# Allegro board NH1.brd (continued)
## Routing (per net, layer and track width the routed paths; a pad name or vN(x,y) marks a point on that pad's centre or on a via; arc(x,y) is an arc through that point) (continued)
M0_DATA45: length 17.9
  TOP w0.102: U1.R22 v1(15.4,58.77)
  BOTTOM w0.102: 15.71,60.05 15.71,59.76 15.73,59.74 15.73,59.1 v1(15.4,58.77)
  BOTTOM w0.14: 15.71,60.05 15.71,62.79 14.51,63.99 14.51,64.19 15,64.67 15,64.81 14.74,65.07 14.74,65.21 14.84,65.31 14.99,65.31 15.24,65.06 15.38,65.06 15.48,65.16 15.48,65.3 15.23,65.55 15.23,65.69 15.33,65.79 15.47,65.79 15.72,65.54 15.87,65.54 16.01,65.69 17.38,65.69 18.53,66.83 19.49,66.83 20.15,67.49 20.15,69.55 19.75,69.96 U1AM4.C2
M0_DATA46: length 17.6
  TOP w0.102: U1.V22 v1(17.4,58.77)
  BOTTOM w0.14: U1AM4.A7 23.75,68.05 23.75,66.27 23.62,66.15 23.48,66.15 23.22,66.41 23.08,66.41 22.98,66.31 22.98,66.17 23.24,65.91 23.24,65.77 22.55,65.08 20.99,65.08 20.19,64.28 20.19,64.14 20.6,63.74 20.6,63.59 20.5,63.49 20.35,63.49 19.95,63.9 19.81,63.9 19.71,63.8 19.71,63.66 20.11,63.25 20.11,63.11 20.01,63.01 19.87,63.01 19.47,63.41 19.32,63.41 19.06,63.15 19.06,61.59 18.34,60.87 17.54,60.87 17.4,60.73 v1(17.4,58.77)
M0_DATA47: length 18
  TOP w0.102: v1(16.08,61.55) 15.73,61.21 U1.T25
  BOTTOM w0.14: v1(16.08,61.55) 16.08,62.96 16.17,63.05 16.17,63.19 15.19,64.17 15.19,64.31 15.29,64.41 15.44,64.41 16.41,63.44 16.55,63.44 16.65,63.54 16.65,63.68 15.68,64.66 15.68,64.8 15.78,64.9 15.92,64.9 16.9,63.92 17.04,63.92 17.15,64.03 17.15,64.23 16.32,65.05 16.32,65.19 16.46,65.33 16.7,65.33 17.08,64.95 17.26,64.95 18.78,66.48 19.59,66.48 20.55,67.43 U1AM4.A3
M0_DATA48: length 22.8
  TOP w0.102: U1.AB22 v1(20.04,58.77)
  IN1 w0.102: v1(20.04,58.77) 21.34,60.07 21.35,60.2 21.16,60.38 21.16,60.5 21.25,60.59 21.38,60.59 21.56,60.41 21.69,60.41 21.8,60.53 21.8,60.91 21.41,61.31 21.41,61.43 21.5,61.52 21.62,61.52 21.94,61.21 22.06,61.21 22.15,61.3 22.15,61.43 21.84,61.74 21.84,61.86 21.93,61.95 22.06,61.95 22.37,61.64 22.49,61.64 22.58,61.73 22.58,61.86 22.27,62.17 22.27,62.3 22.36,62.39 22.49,62.39 22.8,62.07 22.92,62.07 23.01,62.16 23.01,62.29 22.7,62.6 22.7,62.73 22.79,62.82 22.92,62.82 23.23,62.5 23.36,62.5 23.48,62.63 23.48,63.1 24.24,63.86 24.24,70.44 23.76,70.92 23.76,73.17 v1(24.15,73.56)
  BOTTOM w0.14: U1AM4.H7 23.75,73.96 v1(24.15,73.56)
M0_DATA49: length 21.9
  TOP w0.102: U1.AC22 v1(20.7,58.77)
  IN1 w0.102: v1(20.7,58.77) 22.11,60.18 22.11,60.79 22.47,61.15 22.6,61.15 22.87,60.89 22.99,60.89 23.08,60.97 23.08,61.1 22.82,61.37 22.82,61.49 22.9,61.58 23.03,61.58 23.3,61.32 23.42,61.32 23.51,61.41 23.51,61.53 23.25,61.8 23.25,61.93 23.83,62.5 23.83,63.01 24.56,63.74 24.56,66.15 24.65,66.23 24.91,66.23 25,66.32 25,66.45 24.91,66.54 24.65,66.54 24.56,66.63 24.56,66.78 24.65,66.86 24.91,66.86 25,66.95 25,67.08 24.91,67.17 24.65,67.17 24.56,67.26 24.56,68.46 24.65,68.55 24.91,68.55 25,68.64 25,68.76 24.91,68.85 24.65,68.85 24.56,68.94 24.56,69.07 24.65,69.16 24.91,69.16 25,69.25 25,69.37 24.91,69.46 24.65,69.46 24.56,69.55 24.56,69.68 24.65,69.77 24.91,69.77 25,69.85 25,69.98 24.91,70.07 24.65,70.07 24.56,70.16 24.56,70.29 24.65,70.38 24.91,70.38 25,70.46 25,70.59 24.91,70.68 24.65,70.68 24.56,70.77 24.56,71.55 v1(24.15,71.96)
  BOTTOM w0.14: U1AM4.F8 v1(24.15,71.96)
M0_DATA50: length 22.6
  TOP w0.102: U1.Y19 v1(18.75,56.78)
  IN1 w0.102: v1(17.96,72.05) 18.6,72.05 18.93,71.71 18.93,62.46 17.06,60.59 17.06,56.58 17.31,56.33 18.3,56.33 v1(18.75,56.78)
  BOTTOM w0.14: U1AM4.G2 19.34,73.56 18.65,73.56 18.12,73.03 18.12,72.72 17.91,72.51 17.91,72.1 v1(17.96,72.05)
M0_DATA51: length 21.5
  TOP w0.102: v1(21.32,58.76) 21.02,58.46 U1.AD22
  IN1 w0.102: v1(24.15,72.76) 24.56,72.34 25.13,72.34 25.32,72.15 25.32,69.86 25.41,69.77 25.68,69.77 25.77,69.68 25.77,69.56 25.68,69.47 25.41,69.47 25.32,69.38 25.32,68.45 25.41,68.36 25.7,68.36 25.79,68.27 25.79,68.15 25.7,68.06 25.41,68.06 25.32,67.97 25.32,67.84 25.41,67.75 25.7,67.75 25.79,67.66 25.79,67.54 25.7,67.45 25.41,67.45 25.32,67.36 25.32,66.13 24.93,65.74 24.93,62.35 24.79,62.21 24.66,62.21 24.37,62.49 24.25,62.49 24.16,62.41 24.16,62.28 24.44,61.99 24.44,61.87 24.36,61.78 24.23,61.78 23.94,62.06 23.82,62.06 23.73,61.97 23.73,61.85 24.01,61.56 24.01,61.44 21.33,58.76 v1(21.32,58.76)
  BOTTOM w0.14: U1AM4.F7 v1(24.15,72.76)
M0_DATA52: length 22.2
  TOP w0.102: U1.AA22 v1(19.38,58.77)
  IN1 w0.102: v1(25.85,74.17) 25.55,73.87 25.55,72.75 26.1,72.19 26.1,66.49 25.23,65.61 25.23,62.19 21.45,58.4 19.75,58.4 v1(19.38,58.77)
  BOTTOM w0.14: U1AM4.H8 24.9,74.31 25.58,74.31 v1(25.85,74.17)
M0_DATA53: length 22.9
  TOP w0.102: U1.Y23 18.7,58.78 v1(18.72,58.78)
  IN1 w0.102: v1(21.32,71.56) 20.83,71.56 20.57,71.31 20.57,70.3 20.69,70.19 21.32,70.19 21.42,70.08 21.42,69.96 21.33,69.87 20.7,69.87 20.61,69.78 20.61,69.66 20.7,69.57 21.33,69.57 21.42,69.48 21.42,68.45 21.33,68.36 20.6,68.36 20.51,68.27 20.51,68.15 20.6,68.06 21.33,68.06 21.42,67.97 21.42,67.39 21.88,66.93 21.88,65.26 21.97,65.17 22.65,65.17 22.74,65.08 22.74,64.95 22.65,64.86 21.97,64.86 21.88,64.78 21.88,64.65 21.97,64.56 22.65,64.56 22.74,64.47 22.74,64.34 22.65,64.25 21.97,64.25 18.72,61 v1(18.72,58.78)
  BOTTOM w0.14: U1AM4.E3 20.86,71.56 v1(21.32,71.56)
M0_DATA54: length 23.1
  TOP w0.102: U1.Y20 v1(18.06,57.47)
  IN1 w0.102: v1(18.06,57.47) 17.73,57.8 17.73,59.75 17.56,59.91 17.56,60.66 19.31,62.42 19.31,62.54 21.14,64.37 21.14,65.21 21.05,65.3 20.83,65.3 20.74,65.39 20.74,65.51 20.83,65.6 21.05,65.6 21.14,65.69 21.14,65.83 21.05,65.92 19.84,65.92 19.75,66.01 19.75,66.18 19.84,66.26 20.29,66.26 20.38,66.35 20.38,66.48 20.29,66.57 19.84,66.57 19.75,66.66 19.75,71.42 20.88,72.55 v1(21.52,72.55)
  BOTTOM w0.14: U1AM4.H3 21.52,72.98 v1(21.52,72.55)
M0_DATA55: length 22.3
  TOP w0.102: U1.Y21 v1(18.7,57.46)
  IN1 w0.102: v1(20.15,71.2) 20.15,69.35 20.24,69.26 20.57,69.26 20.66,69.17 20.66,69.05 20.57,68.96 20.24,68.96 20.15,68.87 20.15,67.73 20.24,67.64 21.03,67.64 21.12,67.55 21.12,67.42 21.03,67.34 20.24,67.34 20.15,67.25 20.15,67.04 20.25,66.93 21.45,66.93 21.55,66.83 21.55,66.65 21.46,66.57 20.77,66.57 20.69,66.48 20.69,66.35 20.77,66.26 21.46,66.26 21.55,66.17 21.55,64.29 18.39,61.13 18.39,57.79 v1(18.7,57.46)
  BOTTOM w0.14: U1AM4.F2 20.15,71.95 v1(20.15,71.2)
M0_DATA56: length 24.5
  TOP w0.102: U1.T22 v1(16.06,58.77)
  TOP w0.14: U1AM3.F7 20.97,71.94 21.47,71.94 21.72,71.69 21.72,71.07 v1(21.33,70.68)
  IN2 w0.102: v1(21.33,70.68) 16.42,65.77 16.42,65.54 16.51,65.45 17.14,65.45 17.23,65.36 17.23,65.24 17.14,65.15 16.51,65.15 16.42,65.06 16.42,64.93 16.51,64.84 17.14,64.84 17.23,64.75 17.23,64.63 17.14,64.54 16.51,64.54 16.42,64.45 16.42,64.32 16.51,64.23 17.14,64.23 17.23,64.14 17.23,64.02 17.14,63.93 16.51,63.93 16.42,63.84 16.42,63.71 16.51,63.62 17.14,63.62 17.23,63.53 17.23,63.41 17.14,63.32 16.51,63.32 16.42,63.23 16.42,63.1 16.51,63.01 17.14,63.01 17.23,62.92 17.23,62.8 17.14,62.71 16.51,62.71 16.42,62.62 16.42,60.74 15.73,60.05 15.73,59.1 v1(16.06,58.77)
M0_DATA57: length 25.1
  TOP w0.102: U1.T20 v1(16.06,57.47)
  TOP w0.14: v1(17.97,71.18) 18.76,71.96 19.14,71.96 19.54,72.36 U1AM3.F8
  IN2 w0.102: v1(16.06,57.47) 15.2,57.47 14.88,57.16 14.61,57.16 14.41,57.35 14.41,59.19 14.51,59.29 14.51,60.43 14.31,60.63 14.31,62.72 14.74,63.16 14.98,63.16 15.07,63.25 15.07,63.37 14.98,63.46 14.53,63.46 14.44,63.55 14.44,63.68 14.53,63.77 14.98,63.77 15.07,63.85 15.07,63.98 14.98,64.07 14.53,64.07 14.44,64.16 14.44,64.29 14.53,64.38 14.98,64.38 15.07,64.46 15.07,64.59 14.98,64.68 14.53,64.68 14.44,64.77 14.44,64.9 14.53,64.98 14.98,64.98 15.07,65.07 15.07,65.2 14.98,65.29 14.53,65.29 14.44,65.38 14.44,65.51 14.53,65.59 14.98,65.59 15.07,65.68 15.07,65.81 14.98,65.9 14.6,65.9 14.51,65.99 14.51,66.45 16.85,68.79 16.85,70.06 v1(17.97,71.18)
M0_DATA58: length 23
  TOP w0.102: U1.W20 v1(18.04,56.79)
  TOP w0.14: U1AM3.F2 24.55,72.36 v1(24.95,71.96)
  IN2 w0.102: v1(18.04,56.79) 18.37,57.12 19.56,57.12 19.71,57.27 19.71,59.73 19.92,59.95 19.92,60.61 21.28,61.97 21.28,63.72 21.73,64.17 21.73,64.3 21.21,64.82 21.21,64.94 21.3,65.03 21.42,65.03 21.95,64.51 22.07,64.51 22.16,64.6 22.16,64.73 21.64,65.25 21.64,65.37 21.73,65.46 21.86,65.46 22.38,64.94 22.5,64.94 24.57,67.01 24.57,71.59 v1(24.95,71.96)
M0_DATA59: length 24
  TOP w0.102: U1.V20 v1(16.72,56.79)
  TOP w0.14: U1AM3.H8 19.75,73.96 19.39,74.31 18.62,74.31 17.74,73.44 v1(17.74,72.88)
  IN2 w0.102: v1(16.72,56.79) 16.38,57.13 15.28,57.13 15,56.85 14.54,56.85 13.75,57.64 13.75,68.89 v1(17.74,72.88)
M0_DATA60: length 24.1
  TOP w0.102: U1.U21 v1(16.73,58.12)
  TOP w0.14: U1AM3.H3 24.05,74.26 v1(24.15,74.36)
  IN2 w0.102: v1(16.73,58.12) 17.39,58.12 17.73,58.46 17.73,59.67 17.93,59.87 18.15,59.87 19.64,61.37 19.64,61.93 19.73,62.02 20.06,62.02 20.15,62.11 20.15,62.24 20.06,62.33 19.73,62.33 19.64,62.42 19.64,62.54 19.73,62.63 20.06,62.63 20.15,62.72 20.15,62.85 20.06,62.94 19.73,62.94 19.64,63.03 19.64,63.15 19.73,63.24 20.06,63.24 20.15,63.33 20.15,63.46 20.06,63.55 19.73,63.55 19.64,63.64 19.64,63.76 19.73,63.85 20.06,63.85 20.15,63.94 20.15,64.07 20.06,64.16 19.73,64.16 19.64,64.24 19.64,64.44 23.75,68.55 23.75,73.97 v1(24.15,74.36)
M0_DATA61: length 24.1
  TOP w0.102: U1.W21 v1(18.06,58.12)
  TOP w0.14: v1(24.15,71.16) 23.75,71.56 U1AM3.E3
  IN2 w0.102: v1(24.15,71.16) 24.15,68.46 23.37,67.68 23.37,67.56 23.84,67.09 23.84,66.96 23.75,66.87 23.62,66.87 23.15,67.34 23.02,67.34 22.93,67.25 22.93,67.13 23.4,66.66 23.4,66.53 23.32,66.44 23.19,66.44 22.72,66.91 22.59,66.91 22.5,66.82 22.5,66.69 22.97,66.22 22.97,66.1 22.88,66.01 22.76,66.01 22.29,66.48 22.16,66.48 20.48,64.8 20.48,64.51 20.57,64.42 20.88,64.42 20.97,64.33 20.97,64.21 20.88,64.12 20.57,64.12 20.48,64.03 20.48,63.9 20.57,63.81 20.88,63.81 20.97,63.72 20.97,63.6 20.88,63.51 20.57,63.51 20.48,63.42 20.48,63.29 20.57,63.2 20.88,63.2 20.97,63.11 20.97,62.99 20.88,62.9 20.57,62.9 20.48,62.81 20.48,62.68 20.57,62.59 20.88,62.59 20.97,62.5 20.97,62.38 20.88,62.29 20.57,62.29 20.48,62.2 20.48,61.73 18.39,59.63 18.39,58.45 v1(18.06,58.12)
M0_DATA62: length 24.5
  TOP w0.102: U1.U20 v1(16.73,57.47)
  TOP w0.14: U1AM3.G2 v1(24.95,73.56)
  IN2 w0.102: v1(16.73,57.47) 17.07,57.14 17.07,56.53 17.17,56.43 18.97,56.43 19.29,56.75 19.72,56.75 20.15,57.18 20.15,57.46 20.76,58.07 21.24,58.07 21.68,58.5 21.68,63.17 25.35,66.85 25.35,73.16 v1(24.95,73.56)
M0_DATA63: length 24.9
  TOP w0.102: U1.T21 v1(16.06,58.12)
  TOP w0.14: U1AM3.H7 20.15,73.56 18.74,73.56 18.38,73.2 v1(18.38,72.41)
  IN2 w0.102: v1(16.06,58.12) 15.59,58.12 15.07,58.64 15.07,59.1 15,59.17 15,60.97 15.4,61.37 15.4,61.95 15.49,62.04 15.97,62.04 16.06,62.13 16.06,62.26 15.97,62.35 15.49,62.35 15.4,62.43 15.4,62.56 15.49,62.65 15.97,62.65 16.06,62.74 16.06,62.87 15.97,62.96 15.49,62.96 15.4,63.04 15.4,63.17 15.49,63.26 15.97,63.26 16.06,63.35 16.06,63.48 15.97,63.56 15.49,63.56 15.4,63.65 15.4,63.78 15.49,63.87 15.97,63.87 16.06,63.96 16.06,64.09 15.97,64.17 15.49,64.17 15.4,64.26 15.4,66.88 18.78,70.26 18.78,71.05 18.38,71.46 v1(18.38,72.41)
M0_DM0: length 18.2
  TOP w0.102: U1.A20 5.33,57.61 4.49,57.61 4.48,57.6
  TOP w0.14: v1(4.24,57.15) 4.24,57.49 4.36,57.6 4.48,57.6
  BOTTOM w0.14: v1(4.24,57.15) 4.43,57.33 4.43,61.52 6.94,64.04 6.94,70.21 6.39,70.76 5.75,70.76 5.75,70.76 U1AM2.D3
M0_DM1: length 19.6
  TOP w0.102: U1.D21 v1(7.47,58.1)
  IN1 w0.102: v1(7.47,58.1) 7.14,58.43 7.14,59.12 7,59.26 7,61.86 6.91,61.95 6.42,61.95 6.33,62.04 6.33,62.17 6.42,62.26 6.91,62.26 7,62.35 7,62.47 6.91,62.56 6.42,62.56 6.33,62.65 6.33,62.78 6.42,62.87 6.91,62.87 7,62.96 7,63.08 6.91,63.17 6.42,63.17 6.33,63.26 6.33,63.39 6.42,63.48 6.91,63.48 7,63.56 7,63.69 6.91,63.78 6.42,63.78 6.33,63.87 6.33,64 6.42,64.09 6.91,64.09 7,64.17 7,70.75 7.77,71.53 v1(7.78,71.53)
  BOTTOM w0.14: v1(7.78,71.53) 8.51,71.56 U1AM2.E7
M0_DM2: length 13.6
  TOP w0.14: U1.D25 7.81,60.43 7.81,61.24 5.7,63.35 5.7,65.16 6.46,65.92 7.55,65.92 7.78,66.15 7.78,67.85 7.17,68.46 7.17,69.43 U1AM1.D3
M0_DM3: length 21.3
  TOP w0.102: U1.F19 9.12,56.45 v1(9.43,56.76)
  TOP w0.14: U1AM1.E7 v1(5.71,71.16)
  IN2 w0.102: v1(5.71,71.16) 5.71,70.79 5.39,70.47 5.39,69.73 6.38,68.74 6.38,68.61 6.1,68.33 6.1,68.21 6.19,68.12 6.32,68.12 6.6,68.4 6.73,68.4 6.82,68.31 6.82,68.18 6.54,67.9 6.54,67.78 6.62,67.69 6.75,67.69 7.03,67.97 7.16,67.97 7.25,67.88 7.25,67.75 6.97,67.47 6.97,67.34 7.06,67.25 7.18,67.25 7.46,67.53 7.59,67.53 7.68,67.44 7.68,67.32 7.4,67.04 7.4,66.91 7.49,66.82 7.61,66.82 7.89,67.1 8.02,67.1 9.38,65.74 9.38,65.24 9.62,65 9.62,61.32 9.83,61.12 9.83,57.16 v1(9.43,56.76)
M0_DM4: length 13.6
  TOP w0.102: 20.7,60.81 20.7,60.23 20.37,59.9 U1.AC24
  TOP w0.14: 20.7,60.81 20.7,61.17 21.22,61.69 21.22,62.82 22.08,63.68 22.95,63.68 23.43,64.17 23.43,66.35 22.92,66.86 22.92,67.9 22.57,68.25 22.57,69.58 U1AM3.D3
M0_DM5: length 15.1
  TOP w0.102: v1(17.84,62.36) 17.84,61.35 17.46,60.97 17.46,60.14 U1.V24
  BOTTOM w0.14: v1(17.84,62.36) 17.49,62.72 17.49,63.4 21.37,67.29 22.36,67.29 22.62,67.54 22.62,67.92 22.16,68.38 22.16,69.32 20.89,70.59 20.72,70.59 20.55,70.76 U1AM4.D3
M0_DM6: length 23
  TOP w0.102: U1.Y22 v1(18.72,58.13)
  IN1 w0.102: v1(23.35,71.16) 22.95,71.56 21.88,71.56 21.73,71.4 21.73,67.62 21.98,67.37 23.05,67.37 23.15,67.26 23.15,67.11 23.06,67.02 22.27,67.02 22.18,66.93 22.18,66.8 22.27,66.71 23.06,66.71 23.15,66.62 23.15,66.5 23.06,66.41 22.27,66.41 22.18,66.32 22.18,66.19 22.27,66.1 23.06,66.1 23.15,66.01 23.15,64.29 22.74,63.89 22.13,63.89 19.05,60.8 19.05,58.46 v1(18.72,58.13)
  BOTTOM w0.14: U1AM4.E7 v1(23.35,71.16)
M0_DM7: length 21
  TOP w0.102: U1.T23 v1(16.07,59.42)
  TOP w0.14: U1AM3.E7 v1(20.95,71.16)
  IN2 w0.102: v1(16.07,59.42) 16.07,59.91 18.25,62.08 18.25,62.82 18.16,62.9 17.8,62.9 17.71,62.99 17.71,63.12 17.8,63.21 18.16,63.21 18.25,63.3 18.25,63.43 18.16,63.51 17.8,63.51 17.71,63.6 17.71,63.73 17.8,63.82 18.16,63.82 18.25,63.91 18.25,64.03 18.16,64.12 17.8,64.12 17.71,64.21 17.71,64.34 17.8,64.43 18.16,64.43 18.25,64.52 18.25,64.64 18.16,64.73 17.8,64.73 17.71,64.82 17.71,64.95 17.8,65.04 18.16,65.04 18.25,65.13 18.25,65.25 18.16,65.34 17.8,65.34 17.71,65.43 17.71,65.56 17.8,65.65 18.16,65.65 18.25,65.74 18.25,65.86 18.16,65.95 17.8,65.95 17.71,66.04 17.71,66.17 17.8,66.26 18.16,66.26 18.25,66.35 18.25,67.16 20.86,69.77 21.12,69.77 21.69,70.34 21.69,70.97 21.5,71.16 v1(20.95,71.16)
M0_DQS0_DN: length 18.3
  TOP w0.131: U1.C19 7.04,56.54 5.78,56.54 5.63,56.4 v1(5.4,56.4)
  BOTTOM w0.131: U1AM2.B7 8.51,69.36 8.43,69.43 7.91,69.43 7.7,69.21 7.7,63.67 5.09,61.07 5.09,59.77 5.19,59.67 5.45,59.67 5.55,59.57 5.55,59.43 5.45,59.33 5.19,59.33 5.09,59.24 5.09,59.1 5.19,59 5.45,59 5.55,58.9 5.55,58.76 5.45,58.67 5.19,58.67 5.09,58.57 5.09,57.66 5.4,57.35 v1(5.4,56.4)
M0_DQS0_DP: length 18.3
  TOP w0.131: v1(4.9,56.82) 5.58,56.82 5.62,56.77 7.46,56.77 U1.D19
  BOTTOM w0.131: U1AM2.C7 8.51,69.76 8.4,69.66 7.82,69.66 7.47,69.31 7.47,63.77 4.86,61.17 4.86,57.56 5.17,57.26 5.17,57.09 v1(4.9,56.82)
M0_DQS1_DN: length 20.4
  TOP w0.102: U1.C21 v1(6.81,58.1)
  IN1 w0.117: v1(6.81,58.1) 6.81,58.13 6.01,58.92 6.01,61.11 5.88,61.24 5.25,61.24 4.97,61.52 4.97,64.45 5.25,64.72 6.08,64.72 6.19,64.84 6.19,64.99 6.1,65.08 5.9,65.08 5.65,65.33 5.65,65.69 5.9,65.94 6.1,65.94 6.19,66.04 6.19,66.17 6.1,66.26 5.93,66.26 5.67,66.51 5.67,66.87 5.93,67.12 6.1,67.12 6.19,67.21 6.19,67.35 6.1,67.44 5.93,67.44 5.67,67.69 5.67,68.05 5.93,68.3 6.09,68.3 6.18,68.39 6.18,71.2 5.73,71.65 5.73,72.23 5.94,72.44 v1(5.94,72.72)
  BOTTOM w0.131: U1AM2.G3 5.31,72.9 5.49,72.72 v1(5.94,72.72)
M0_DQS1_DP: length 20.3
  TOP w0.102: U1.C22 v1(6.81,58.78)
  IN1 w0.117: v1(6.81,58.78) 6.54,58.78 6.28,59.03 6.28,59.26 6.38,59.35 6.52,59.35 6.61,59.45 6.61,59.58 6.52,59.67 6.38,59.67 6.28,59.77 6.28,59.9 6.38,59.99 6.52,59.99 6.61,60.09 6.61,60.22 6.52,60.31 6.38,60.31 6.28,60.41 6.28,61.22 5.99,61.51 5.36,61.51 5.24,61.63 5.24,64.34 5.36,64.46 6.19,64.46 6.46,64.73 6.46,65.1 6.21,65.35 6.01,65.35 5.92,65.45 5.92,65.58 6.01,65.67 6.21,65.67 6.46,65.92 6.46,66.28 6.21,66.53 6.04,66.53 5.94,66.62 5.94,66.76 6.04,66.85 6.21,66.85 6.46,67.1 6.46,67.46 6.21,67.71 6.04,67.71 5.94,67.8 5.94,67.94 6.04,68.03 6.2,68.03 6.45,68.28 6.45,71.31 6,71.76 6,72.12 6.06,72.18 v1(6.22,72.18)
  BOTTOM w0.131: v1(6.22,72.18) 6.05,72.35 5.76,72.35 5.62,72.49 5.44,72.49 U1AM2.F3
M0_DQS2_DN: length 12.5
  TOP w0.131: U1.C25 7.13,60.99 5.04,63.08 5.04,65.55 6.15,66.67 6.15,67.1 6.06,67.2 5.8,67.2 5.7,67.3 5.7,67.43 5.8,67.53 6.06,67.53 6.15,67.63 6.15,67.77 6.06,67.87 5.8,67.87 5.7,67.96 5.7,68.1 5.8,68.2 6.06,68.2 6.15,68.3 6.15,68.97 5.68,69.44 5.42,69.44 5.31,69.33 U1AM1.B7
M0_DQS2_DP: length 12.4
  TOP w0.102: U1.C24 7.47,60.08 7.47,60.57
  TOP w0.131: 7.47,60.57 7.36,60.67 7.36,61.08 5.27,63.18 5.27,65.46 6.39,66.57 6.39,69.07 5.78,69.68 5.42,69.68 5.31,69.79 U1AM1.C7
M0_DQS3_DN: length 21.9
  TOP w0.102: U1.H19 v1(10.76,56.13)
  TOP w0.131: U1AM1.G3 8.51,72.97 7.69,72.15 7.53,72.15 7.09,71.71 v1(6.83,71.71)
  IN2 w0.117: v1(6.83,71.71) 6.19,71.07 6.19,69.72 6.57,69.35 6.97,69.35 7.2,69.58 7.37,69.58 7.52,69.43 7.52,69.29 7.33,69.1 7.33,68.43 9.68,66.08 10.01,66.08 10.28,65.81 10.28,65.03 10.14,64.89 10.14,56.87 10.76,56.25 v1(10.76,56.13)
M0_DQS3_DP: length 21.8
  TOP w0.102: U1.H20 v1(10.76,56.82)
  TOP w0.131: U1AM1.F3 8.23,72.36 7.79,71.92 7.63,71.92 7.25,71.54 v1(6.84,71.13)
  IN2 w0.117: v1(6.84,71.13) 6.61,71.13 6.46,70.98 6.46,69.83 6.68,69.62 6.86,69.62 7.09,69.84 7.48,69.84 7.79,69.54 7.79,69.18 7.59,68.99 7.59,68.54 9.79,66.35 10.12,66.35 10.55,65.92 10.55,64.91 10.41,64.78 10.41,62.14 10.51,62.05 10.79,62.05 10.88,61.95 10.88,61.82 10.79,61.73 10.51,61.73 10.41,61.63 10.41,61.5 10.51,61.41 10.79,61.41 10.88,61.31 10.88,61.18 10.79,61.09 10.51,61.09 10.41,60.99 10.41,56.98 10.58,56.82 v1(10.76,56.82)
M0_DQS4_DN: length 13.6
  TOP w0.131: U1.AB24 20.03,60.06 20.03,62.62 21.72,64.31 22.61,64.31 22.74,64.44 22.74,64.7 22.62,64.82 22.06,64.82 21.77,65.11 21.77,65.59 21.42,65.95 21.42,67.97 21.65,68.2 21.65,69.2 21.4,69.44 20.68,69.44 20.55,69.31 U1AM3.B7
M0_DQS4_DP: length 13.7
  TOP w0.131: U1AM3.C7 20.55,69.81 20.68,69.68 21.5,69.68 21.88,69.29 21.88,68.11 21.65,67.87 21.65,66.05 22.01,65.69 22.01,65.21 22.16,65.05 22.72,65.05 22.97,64.8 22.97,64.34 22.71,64.08 21.82,64.08 20.27,62.53 20.27,62.22 20.36,62.12 20.49,62.12 20.58,62.02 20.58,61.88 20.49,61.79 20.36,61.79 20.27,61.69 20.27,60.5 U1.AC25
M0_DQS5_DN: length 16.3
  TOP w0.131: v1(16.9,61.8) 16.9,61.8 17.06,61.64 17.06,61.46 16.62,61.01 16.62,60.61 U1.U25
  BOTTOM w0.131: v1(16.9,61.8) 17.28,61.42 18.17,61.42 18.63,61.88 18.63,62.64 18.33,62.94 18.33,63.23 20.86,65.76 21.15,65.76 21.45,65.46 21.85,65.46 22.07,65.68 22.07,66.03 21.78,66.32 21.78,66.49 21.91,66.63 22.67,66.63 23.28,67.23 23.28,68.31 22.89,68.69 22.89,69.14 23.2,69.45 23.63,69.45 23.75,69.33 U1AM4.B7
M0_DQS5_DP: length 16.4
  TOP w0.131: U1.V25 16.85,60.62 16.85,60.92 17.29,61.36 17.29,61.64 v1(17.46,61.8)
  BOTTOM w0.131: U1AM4.C7 23.75,69.76 23.66,69.68 23.45,69.68 23.09,70.04 22.95,70.04 22.81,69.91 22.81,69.73 22.92,69.63 22.92,69.5 22.66,69.24 22.66,68.6 23.04,68.21 23.04,67.33 22.57,66.86 21.82,66.86 21.55,66.59 21.55,66.23 21.84,65.94 21.84,65.78 21.76,65.7 21.54,65.7 21.24,66 20.76,66 18.09,63.33 18.09,62.85 18.4,62.55 18.4,61.97 18.08,61.65 17.61,61.65 v1(17.46,61.8)
M0_DQS6_DN: length 21.7
  TOP w0.102: U1.AA23 v1(19.38,59.42)
  IN1 w0.117: v1(19.38,59.42) 19.77,59.81 19.77,60.73 22.5,63.47 22.91,63.47 23.57,64.12 23.57,67.64 23.11,68.09 22.43,68.09 22.09,68.42 22.09,69.13 22.39,69.42 23.43,69.42 23.57,69.56 23.57,69.69 23.42,69.84 22.38,69.84 22.09,70.12 22.09,70.72 22.37,71 22.59,71 v1(22.77,71.17)
  BOTTOM w0.131: v1(22.77,71.17) 22.59,70.99 22.41,70.99 22.15,71.25 22.15,71.67 21.65,72.17 21.34,72.17 21.15,72.36 21.15,72.58 20.87,72.87 20.65,72.87 20.55,72.97 U1AM4.G3
M0_DQS6_DP: length 21.8
  TOP w0.102: U1.AB23 v1(20.04,59.42)
  IN1 w0.117: v1(22.77,70.58) 22.62,70.73 22.48,70.73 22.36,70.61 22.36,70.24 22.49,70.11 23.53,70.11 23.84,69.8 23.84,69.45 23.54,69.15 22.5,69.15 22.36,69.02 22.36,68.53 22.54,68.36 23.23,68.36 23.84,67.75 23.84,64.01 23.02,63.2 22.62,63.2 20.04,60.62 20.04,60.27 20.13,60.18 20.39,60.18 20.48,60.08 20.48,59.95 20.39,59.86 20.13,59.86 20.04,59.76 v1(20.04,59.42)
  BOTTOM w0.131: U1AM4.F3 20.55,72.56 20.63,72.64 20.77,72.64 20.92,72.49 20.92,72.26 21.25,71.94 21.55,71.94 21.91,71.57 21.91,71.16 22.31,70.76 22.59,70.76 v1(22.77,70.58)
M0_DQS7_DN: length 23.2
  TOP w0.102: U1.U23 v1(16.73,59.42)
  TOP w0.131: U1AM3.G3 23.75,72.89 23.28,72.43 v1(23.12,72.43)
  IN2 w0.117: v1(16.73,59.42) 16.85,59.3 17.02,59.3 17.16,59.44 17.16,60.48 18.79,62.12 18.79,65.62 19.13,65.97 19.13,66.1 18.88,66.35 18.88,66.7 19.13,66.96 19.49,66.96 20.24,66.21 20.37,66.21 20.46,66.3 20.46,66.44 19.72,67.18 19.72,67.54 19.97,67.79 20.32,67.79 21.07,67.04 21.2,67.04 21.3,67.14 21.3,67.27 21.04,67.52 21.04,67.88 22.59,69.42 22.79,69.42 22.88,69.51 22.88,69.65 22.79,69.74 22.38,69.74 22.13,69.99 22.13,71.6 22.76,72.24 22.95,72.25 v1(23.12,72.43)
M0_DQS7_DP: length 23.3
  TOP w0.102: U1.U22 v1(16.73,58.77)
  TOP w0.131: v1(23.16,71.89) 23.63,72.36 U1AM3.F3
  IN2 w0.117: v1(23.16,71.89) 23.06,71.98 22.88,71.98 22.4,71.49 22.4,70.1 22.49,70.01 22.9,70.01 23.15,69.76 23.15,69.4 22.9,69.15 22.7,69.15 21.31,67.77 21.31,67.63 21.57,67.38 21.57,67.03 21.31,66.77 20.96,66.77 20.21,67.52 20.08,67.52 19.98,67.43 19.98,67.29 20.73,66.55 20.73,66.19 20.48,65.94 20.12,65.94 19.38,66.69 19.24,66.69 19.15,66.59 19.15,66.46 19.4,66.21 19.4,65.85 19.06,65.51 19.06,62.01 18.25,61.2 18.25,61.06 18.32,60.99 18.32,60.86 18.23,60.77 18.09,60.77 18.02,60.84 17.89,60.84 17.42,60.37 17.42,59.33 17.13,59.03 16.99,59.03 v1(16.73,58.77)
M0_DRAMRSTB: length 64.7
  TOP w0.102: U1.U19 v1(16.08,56.78) ; 22.84,82.71 v1(21.94,82.71)
  TOP w0.14: 22.84,82.71 24.55,81 24.55,80.71 U1AM3.T2 ; U1AM1.T2 9.31,81.06 7.66,82.71 v1(7.25,82.71) ; v1(17.96,84.87) 17.96,77.44 16.52,76 16.52,73.11 16.7,72.93 16.7,70.77 16.03,70.1 16.03,66.34 16.17,66.2 16.75,66.2 16.95,65.99 16.95,62.9 16.44,62.39 v1(14.97,62.39)
  IN1 w0.102: v1(21.94,82.71) 20.47,84.18 18.65,84.18 v1(17.96,84.87)
  IN2 w0.102: v1(17.96,84.87) 16.09,84.87 15.55,85.4 10.45,85.4 7.75,82.71 v1(7.25,82.71)
  BOTTOM w0.102: v1(16.08,56.78) 15.58,57.28 15.58,58.07 15.07,58.58 15.07,58.9 14.82,59.16 14.82,60.39 15.05,60.62 15.05,61.24 14.64,61.65 14.64,62.06 v1(14.97,62.39) ; 6.28,82.71 v1(7.25,82.71)
  BOTTOM w0.14: U1AM4.T2 19.75,80.9 21.55,82.71 v1(21.94,82.71) ; U1AM2.T2 4.51,80.93 6.28,82.71
M0_MA0: length 58.9
  TOP w0.102: 22.94,77.73 v1(21.89,77.73) ; v1(13.42,61.32) 13.42,60.09 13.08,59.75 U1.M24
  TOP w0.112: v1(7.41,77.73) 7.12,77.73 7.06,77.79 7.06,77.99 7.15,78.08 7.58,78.08 7.7,77.96 7.78,77.96
  TOP w0.14: U1AM3.N3 23.64,77.86 23.06,77.86 22.94,77.73 ; 7.78,77.96 8.04,77.96 U1AM1.N3
  IN1 w0.102: v1(15.37,79.29) 15.69,79.61 16.22,79.61 16.34,79.74 16.34,80.19 16.55,80.4 17.19,80.4 17.35,80.55 17.35,81.44 17.44,81.54 17.59,81.54 17.69,81.44 17.69,80.22 17.52,80.05 16.79,80.05 16.7,79.96 16.7,79.83 16.79,79.75 17.57,79.75 17.66,79.66 17.66,79.53 17.57,79.44 16.46,79.44 16.37,79.35 16.37,79.22 16.46,79.14 17.57,79.14 17.66,79.05 17.66,78.9 17.56,78.8 15.55,78.8 15.38,78.63 15.38,77.46 14.64,76.73 14.64,76.41 14.82,76.23 14.82,75.39 15.05,75.16 15.05,74.94 14.82,74.71 14.82,73.54 15.73,72.63 15.73,65.31 14.62,64.19 14.62,63.4 13.83,62.61 13.83,61.73 v1(13.42,61.32)
  IN2 w0.102: v1(21.89,77.73) 21.3,77.73 19.77,79.25 18.05,79.25 17.96,79.34 17.96,79.49 17.87,79.58 17.74,79.58 17.65,79.49 17.65,79.34 17.56,79.25 17.44,79.25 17.35,79.34 17.35,79.49 17.26,79.58 17.13,79.58 17.04,79.49 17.04,79.38 16.95,79.29 v1(15.37,79.29) 15.02,79.29 14.74,79.57 10.72,79.57 8.88,77.73 v1(7.41,77.73)
  BOTTOM w0.102: 6.37,77.73 v1(7.41,77.73)
  BOTTOM w0.14: U1AM2.N3 6.14,77.96 6.37,77.73 ; v1(21.89,77.73) 21.66,77.96 21.52,77.96 21.42,77.86 21.42,77.78 21.32,77.68 21.18,77.68 21.08,77.78 21.08,77.86 20.98,77.96 U1AM4.N3
M0_MA1: length 58.8
  TOP w0.102: 12.44,61.22 12.53,61.13 12.53,59.2 U1.L23 ; 21.57,78.8 v1(22.65,78.8)
  TOP w0.14: U1AM1.P7 5.65,78.76 6.05,79.16 6.41,79.16 v1(6.78,78.8) ; 12.44,61.22 12.44,61.99 12.83,62.38 12.83,62.51 12.46,62.89 12.46,63.02 12.55,63.11 12.68,63.11 13.06,62.74 13.19,62.74 13.28,62.83 13.28,62.96 12.9,63.34 12.9,63.47 12.99,63.56 13.12,63.56 13.5,63.18 13.63,63.18 13.72,63.27 13.72,63.4 13.35,63.78 13.35,63.91 13.44,64 13.57,64 14.04,63.53 14.26,63.53 14.8,64.07 14.8,72.61 14.26,73.15 14.26,75.94 15.66,77.34 16.51,77.34 17.05,77.88 17.05,78.32 16.95,78.42 16.62,78.42 16.52,78.52 16.52,78.66 16.62,78.76 16.95,78.76 17.05,78.86 17.05,80.12 v1(16.42,80.75) ; 21.57,78.8 21.04,78.8 21.01,78.76 U1AM3.P7
  IN2 w0.102: v1(6.78,78.8) 7.78,78.8 10.32,81.34 11.69,81.34 12.28,80.75 v1(16.42,80.75) 17.28,80.75 17.56,81.03 19.29,81.03 21.53,78.8 22.11,78.8 22.46,79.15 22.8,79.15 23.06,79.41 23.97,79.41 24.08,79.31 24.08,79.17 23.96,79.05 23.24,79.05 22.98,78.8 v1(22.65,78.8)
  BOTTOM w0.102: 7.89,78.8 v1(6.78,78.8)
  BOTTOM w0.112: 22.83,79.15 22.52,79.15 22.41,79.04 22.41,78.91 22.52,78.8 v1(22.65,78.8)
  BOTTOM w0.14: U1AM4.P7 23.53,78.76 23.34,78.95 23.03,78.95 22.83,79.15 ; U1AM2.P7 8.29,78.76 7.92,78.76 7.89,78.8
M0_MA2: length 59.9
  TOP w0.102: 23.16,79.15 v1(21.89,79.15) ; U1.N23 14.08,59.43 14.53,59.43 15,59.9 15,61.8 v1(14.97,61.83)
  TOP w0.14: U1AM3.P3 23.55,78.76 23.16,79.15 ; v1(7.41,79.15) 7.62,79.15 7.76,79.01 7.76,78.76 7.9,78.62 8.06,78.62 8.11,78.67 8.11,78.82 8.18,78.89 8.38,78.89 U1AM1.P3
  IN1 w0.102: v1(14.97,61.83) 15.83,62.69 16.75,62.69 17.33,63.28 17.33,67.8 17.16,67.98 17.16,70.52 16.73,70.94 16.73,74.93 16.24,75.42 15.25,75.42 15.15,75.52 15.15,76.8 15.68,77.34 15.68,78.37 15.8,78.49 17.71,78.49 17.99,78.77 17.99,81.59 17.61,81.97 16.27,81.97 16.09,81.79 16.09,80.95 15.91,80.78 15.55,80.78 v1(15.15,81.18)
  IN2 w0.102: v1(7.41,79.15) 7.71,79.15 10.2,81.64 11.85,81.64 12.3,81.18 13.74,81.18 13.83,81.27 13.83,81.45 13.92,81.54 14.04,81.54 14.13,81.45 14.13,81.27 14.22,81.18 14.35,81.18 14.44,81.27 14.44,81.58 14.53,81.67 14.65,81.67 14.74,81.58 14.74,81.27 14.83,81.18 v1(15.15,81.18) 15.61,81.18 15.71,81.29 15.71,81.57 15.81,81.68 16.03,81.68 16.12,81.59 16.12,81.22 16.2,81.13 16.33,81.13 16.42,81.22 16.42,81.59 16.51,81.68 16.64,81.68 16.73,81.59 16.73,81.22 16.81,81.13 16.94,81.13 17.14,81.34 19.42,81.34 21.6,79.15 v1(21.89,79.15)
  BOTTOM w0.102: 6.31,79.15 7,79.15
  BOTTOM w0.14: U1AM2.P3 5.65,78.76 6.04,79.15 6.31,79.15 ; 7,79.15 v1(7.41,79.15) ; v1(21.89,79.15) 21.5,78.76 20.99,78.76 U1AM4.P3
M0_MA3: length 61.8
  TOP w0.102: 23.09,78.16 22.82,78.44 v1(21.89,78.44) ; v1(13.4,57.47) U1.M20
  TOP w0.112: 7.93,78.31 7.76,78.31 7.63,78.44 v1(7.41,78.44)
  TOP w0.14: U1AM1.N2 9.56,77.96 9.7,78.1 9.7,78.27 9.59,78.39 8.9,78.39 8.82,78.31 7.93,78.31 ; U1AM3.N2 24.12,78.39 23.63,78.39 23.4,78.16 23.09,78.16
  IN1 w0.102: v1(13.4,57.47) 12.74,58.14 12.74,58.65 12.55,58.84 12.55,60.32 12.23,60.64 12.23,63.17 13.09,64.03 13.09,64.93 13.62,65.46 13.62,69.07 13.71,69.16 14.11,69.16 14.2,69.25 14.2,69.37 14.11,69.46 13.71,69.46 13.62,69.55 13.62,69.68 13.71,69.77 14.11,69.77 14.2,69.86 14.2,69.98 14.11,70.07 13.71,70.07 13.62,70.16 13.62,70.36 13.73,70.46 14.07,70.46 14.17,70.57 14.17,72.02 13.28,72.9 13.28,75.51 13.09,75.7 13.09,78.24 12.66,78.67 12.35,78.67 12,79.02 12,80.06 v1(12.29,80.35)
  IN2 w0.102: v1(21.89,78.44) 21.45,78.44 19.16,80.73 17.69,80.73 17.32,80.35 v1(12.29,80.35) 12.11,80.18 11.7,80.18 11.61,80.27 11.61,80.94 11.52,81.03 11.39,81.03 11.3,80.94 11.3,80.27 11.21,80.18 10.55,80.18 10.46,80.27 10.46,80.71 10.37,80.8 10.24,80.8 10.09,80.65 10.09,79.84 9.7,79.44 9.57,79.44 9.28,79.74 9.15,79.74 9.07,79.65 9.07,79.52 9.36,79.23 9.36,79.1 9.27,79.01 9.14,79.01 8.85,79.3 8.72,79.3 8.63,79.22 8.63,79.09 8.93,78.8 8.93,78.67 8.84,78.58 8.71,78.58 8.42,78.87 8.29,78.87 8.16,78.74 8.16,78.54 8.06,78.44 v1(7.41,78.44)
  BOTTOM w0.102: 6.41,78.44 v1(7.41,78.44)
  BOTTOM w0.14: U1AM2.N2 4.88,78.34 6.31,78.34 6.41,78.44 ; U1AM4.N2 19.66,77.87 19.5,77.87 19.36,78.01 19.36,78.21 19.54,78.39 21.84,78.39 v1(21.89,78.44)
M0_MA4: length 66.9
  TOP w0.102: 21.65,80.93 v1(22.65,80.93) ; v1(13.4,58.77) 13.08,58.45 U1.M22
  TOP w0.14: U1AM3.P8 19.75,79.01 20.15,79.42 20.15,79.69 20.42,79.96 20.68,79.96 21.65,80.93 ; v1(6.65,80.93) 6.65,80.79 6.43,80.57 6.03,80.57 5.43,79.97 5.18,79.97 4.91,79.7 4.91,79.36 4.51,78.95 U1AM1.P8
  IN1 w0.102: v1(13.4,58.77) 13.06,59.12 13.06,60.71 12.81,60.95 12.81,62.89 13.7,63.78 13.7,64.57 14.81,65.68 14.81,72.26 13.89,73.18 13.89,75.83 13.72,76.01 13.72,81.75 13.09,82.38 12.14,82.38 12.04,82.48 v1(12.04,83.5) 11.45,82.92 11.45,82.77 11.67,82.56 11.67,82.43 11.58,82.34 11.45,82.34 11.19,82.61 11.06,82.61 10.96,82.5 10.83,82.5 10.59,82.75 10.46,82.75 10.37,82.66 10.37,82.53 10.62,82.29 10.62,82.16 10.53,82.07 10.4,82.07 10.16,82.31 10.03,82.31 9.94,82.22 9.94,82.1 10.19,81.85 10.19,81.73 9.31,80.85 9.16,80.85 9.07,80.76 9.07,80.33 8.98,80.24 8.85,80.24 8.76,80.33 8.76,80.84 8.67,80.93 8.55,80.93 8.46,80.84 8.46,80 8.37,79.91 8.24,79.91 8.15,80 8.15,80.84 8.06,80.93 v1(6.65,80.93)
  IN2 w0.102: v1(12.04,83.5) 15.29,83.5 15.71,83.09 17.31,83.09 17.7,83.48 19.2,83.48 21.75,80.93 v1(22.65,80.93)
  BOTTOM w0.102: 7.66,80.93 v1(6.65,80.93)
  BOTTOM w0.14: U1AM2.P8 9.31,78.97 9.31,79.03 8.92,79.41 8.92,79.69 8.65,79.96 8.37,79.96 7.99,80.35 7.99,80.6 7.66,80.93 ; v1(22.65,80.93) 22.92,80.93 23.12,80.73 23.12,80.19 23.34,79.97 23.95,79.97 24.15,79.77 24.15,79.39 24.34,79.2 24.44,79.2 24.55,79.1 24.55,78.85 U1AM4.P8
M0_MA5: length 63.2
  TOP w0.102: 12.78,61.42 12.78,58.55 12.67,58.45 U1.L22 ; 22.88,79.86 v1(21.89,79.86)
  TOP w0.14: 12.78,61.42 12.78,61.89 13.29,62.41 13.57,62.41 15.1,63.94 15.1,72.74 14.57,73.27 14.57,75.81 15.79,77.03 16.64,77.03 17.35,77.75 17.35,82.64 17.21,82.78 17.02,82.78 16.88,82.64 16.88,82.14 16.74,82 16.06,82 15.64,82.41 v1(14.98,82.41) ; U1AM3.P2 24.13,79.17 23.57,79.17 22.88,79.86 ; U1AM1.P2 9.55,78.76 9.65,78.86 9.65,79.06 9.51,79.2 8.07,79.2 v1(7.41,79.86)
  IN1 w0.102: v1(14.98,82.41) 15.38,82.81 19.01,82.81 19.36,82.45 19.36,82.04 18.76,81.43 18.76,81.31 18.85,81.22 18.97,81.22 19.14,81.38 19.27,81.38 19.36,81.29 19.36,81.17 19.19,81 19.19,80.73 20.05,79.86 v1(21.89,79.86)
  IN2 w0.102: v1(7.41,79.86) 7.96,79.86 10.44,82.35 11.18,82.35 11.29,82.23 11.29,82.03 11.38,81.95 11.51,81.95 11.6,82.03 11.6,82.23 11.69,82.32 11.81,82.32 11.9,82.23 11.9,82.03 11.99,81.95 12.12,81.95 12.21,82.03 12.21,82.23 12.35,82.38 14.87,82.38 14.9,82.41 v1(14.98,82.41)
  BOTTOM w0.102: 6.26,79.86 v1(7.41,79.86)
  BOTTOM w0.14: U1AM2.P2 4.73,78.98 4.92,79.17 5.57,79.17 6.26,79.86 ; v1(21.89,79.86) 21.2,79.17 20.16,79.17 U1AM4.P2
M0_MA6: length 67.2
  TOP w0.102: U1.K24 12.08,60.05 12.08,60.58 11.77,60.89 ; 21.67,82.35 v1(22.65,82.35)
  TOP w0.14: U1AM3.R8 19.75,79.78 20.13,80.16 20.13,80.81 21.67,82.35 ; v1(6.65,82.35) 6.03,82.35 4.89,81.21 4.89,80.13 4.51,79.75 U1AM1.R8 ; v1(15.06,85.03) 14.62,84.58 14.62,82.61 14.39,82.38 14.39,79.54 14.49,79.44 14.85,79.44 14.95,79.34 14.95,79.2 14.85,79.1 14.49,79.1 14.39,79 14.39,76.97 13.65,76.23 13.65,72.89 14.19,72.36 14.19,65.67 11.77,63.26 11.77,60.89
  IN2 w0.102: v1(6.65,82.35) 7.83,82.35 10.51,85.03 10.69,85.03 10.78,84.94 10.78,84.5 10.87,84.41 11,84.41 11.09,84.5 11.09,84.94 11.18,85.03 11.3,85.03 11.39,84.94 11.39,84.5 11.48,84.41 11.61,84.41 11.7,84.5 11.7,84.94 11.79,85.03 v1(15.06,85.03) 15.49,85.03 16.09,84.43 18.45,84.43 18.54,84.52 18.54,84.85 18.63,84.94 18.75,84.94 18.84,84.85 18.84,84.52 18.93,84.43 19.06,84.43 19.15,84.52 19.15,84.85 19.24,84.94 19.36,84.94 19.45,84.85 19.45,84.68 21.78,82.35 v1(22.65,82.35)
  BOTTOM w0.102: 7.43,82.35 v1(6.65,82.35)
  BOTTOM w0.14: 7.43,82.35 8.9,80.88 8.9,80.27 9.31,79.86 U1AM2.R8 ; U1AM4.R8 24.55,79.82 24.12,80.24 24.12,81.63 23.13,82.63 22.93,82.63 v1(22.65,82.35)
M0_MA7: length 62.2
  TOP w0.102: 13.75,61.65 U1.N25 ; v1(22.06,81.28) 22.84,81.28 23.03,81.1 23.03,80.83 23.38,80.47
  TOP w0.14: U1AM3.R2 24.12,79.99 23.62,79.99 23.38,80.23 23.38,80.47 ; v1(15.89,83.44) 16.32,83.88 16.93,83.88 17.66,83.14 17.66,77.62 16.76,76.73 15.91,76.73 14.87,75.68 14.87,73.4 15.41,72.86 15.41,63.81 13.75,62.16 13.75,61.65 ; U1AM1.R2 8.88,79.99 8.37,79.99 8.14,80.22 8.14,81.08 7.94,81.28 7.25,81.28 v1(7.25,81.28)
  IN1 w0.102: v1(22.06,81.28) 20.97,81.28 20.85,81.4 20.85,81.52 21.13,81.8 21.13,81.93 21.04,82.02 20.92,82.02 20.64,81.74 20.51,81.74 20.42,81.83 20.42,81.95 20.7,82.23 20.7,82.36 20.61,82.45 20.49,82.45 20.21,82.17 20.08,82.17 19.99,82.26 19.99,82.39 20.27,82.67 20.27,82.79 20.18,82.88 20.06,82.88 19.9,82.73 19.78,82.73 19.69,82.82 19.69,82.94 19.89,83.15 19.89,83.33 19.8,83.41 19.64,83.41 19.42,83.19 19.24,83.19 18.63,83.8 16.24,83.8 v1(15.89,83.44)
  IN2 w0.102: v1(15.89,83.44) 15.78,83.44 15.32,83.91 9.82,83.91 7.76,81.85 7.76,81.46 7.58,81.28 7.25,81.28 v1(7.25,81.28)
  BOTTOM w0.102: 6.46,81.28 v1(7.25,81.28)
  BOTTOM w0.14: U1AM2.R2 4.93,79.99 5.44,79.99 5.72,80.26 5.72,80.54 6.46,81.28 ; v1(22.06,81.28) 21.7,81.28 20.97,80.55 20.97,80.22 20.73,79.99 20.17,79.99 U1AM4.R2
M0_MA8: length 66.4
  TOP w0.102: 21.75,83.06 22.46,83.06 22.46,83.06 v1(22.51,83.06)
  TOP w0.14: U1AM3.T8 19.75,81.06 21.75,83.06 ; U1AM1.T8 4.51,81.29 6.28,83.06 v1(6.65,83.06) ; U1.J25 11.1,63.49 13.57,65.96 13.57,67.42 13.46,67.53 12.64,67.53 12.49,67.69 12.49,70.23 12.15,70.56 12.15,72.02 13.04,72.9 13.04,76.49 13.78,77.23 13.78,79.27 13.68,79.37 13.22,79.37 13.12,79.47 13.12,79.61 13.22,79.71 13.68,79.71 13.78,79.81 13.78,79.95 13.68,80.05 13.22,80.05 13.12,80.16 13.12,80.3 13.22,80.4 13.68,80.4 13.78,80.5 13.78,80.64 13.68,80.74 13.22,80.74 13.12,80.84 13.12,80.98 13.22,81.08 13.68,81.08 13.78,81.18 v1(13.78,85.77)
  IN2 w0.102: v1(6.65,83.06) 6.65,83.56 7,83.9 7.3,83.9 7.73,83.47 8.08,83.47 10.38,85.77 v1(13.78,85.77) 15.64,85.77 16.16,85.25 19.51,85.25 21.7,83.06 22.46,83.06 22.46,83.06 v1(22.51,83.06)
  BOTTOM w0.102: 7.45,83.06 v1(6.65,83.06)
  BOTTOM w0.14: U1AM4.T8 24.55,80.75 24.55,81.67 23.15,83.06 22.52,83.06 v1(22.51,83.06) ; 7.45,83.06 9.31,81.21 U1AM2.T8
M0_MA9: length 61.5
  TOP w0.102: 22.85,80.57 v1(21.89,80.57)
  TOP w0.14: U1.H24 10.78,60.1 10.78,63.6 12.19,65.01 12.19,65.14 12,65.33 12,65.46 12.09,65.55 12.22,65.55 12.41,65.36 12.54,65.36 12.63,65.45 12.63,65.58 12.44,65.77 12.44,65.9 12.53,66 12.66,66 12.85,65.81 12.98,65.81 13.26,66.09 13.26,66.4 13.17,66.5 12.29,66.5 12.2,66.59 12.2,66.72 12.29,66.81 13.17,66.81 13.26,66.9 13.26,67.12 13.15,67.23 12.32,67.23 12.19,67.36 12.19,70.1 11.85,70.44 11.85,72.14 12.74,73.03 12.74,76.62 13.42,77.3 13.42,78.44 13.1,78.76 12.27,78.76 11.86,79.18 11.86,82.49 12.51,83.14 v1(12.86,83.14) ; v1(7.41,80.57) 7.38,80.61 7.38,80.85 7.5,80.97 7.69,80.97 7.83,80.83 7.83,79.91 8.19,79.56 U1AM1.R3 ; U1AM3.R3 23.62,79.56 23.07,80.11 23.07,80.35 22.85,80.57
  IN2 w0.102: v1(21.89,80.57) 21.65,80.57 19.09,83.14 17.84,83.14 17.43,82.73 15.63,82.73 15.22,83.14 v1(12.86,83.14) 11.75,83.14 11.66,83.23 11.66,83.51 11.57,83.6 11.44,83.6 11.36,83.51 11.36,83.13 11.27,83.04 11.14,83.04 11.05,83.13 11.05,83.51 10.96,83.6 10.83,83.6 10.75,83.51 10.75,83.13 10.66,83.04 10.53,83.04 10.44,83.13 10.44,83.51 10.35,83.6 10.23,83.6 10.14,83.51 10.14,83.18 9.87,82.91 9.55,82.91 9.44,82.81 9.44,82.55 9.35,82.46 9.23,82.46 9.14,82.55 9.02,82.55 8.93,82.46 8.93,82.33 9.01,82.25 9.01,82.12 8.92,82.03 8.8,82.03 8.71,82.11 8.59,82.11 8.5,82.02 8.5,81.9 8.58,81.81 8.58,81.69 8.49,81.6 8.37,81.6 8.28,81.68 8.16,81.68 8.07,81.59 8.07,81.22 v1(7.41,80.57)
  BOTTOM w0.102: 6.46,80.57 v1(7.41,80.57)
  BOTTOM w0.14: 6.46,80.57 5.45,79.56 U1AM2.R3 ; U1AM4.R3 20.88,79.56 21.31,80 21.31,80.36 21.52,80.57 v1(21.89,80.57)
M0_MA10: length 59.7
  TOP w0.102: U1.N20 v1(13.4,56.82) ; 21.65,76.66 22.26,76.66
  TOP w0.14: 21.65,76.66 20.85,76.66 U1AM3.L7 ; 22.26,76.66 v1(22.65,76.66) ; U1AM1.L7 5.75,76.36 6.35,76.36 v1(6.65,76.66)
  IN1 w0.102: v1(12.61,77.48) 12.25,77.48 12.15,77.37 12.15,77.19 12.27,77.07 12.52,77.07 12.61,76.98 12.61,76.86 12.52,76.77 12.04,76.77 11.95,76.68 11.95,76.55 12.04,76.46 12.52,76.46 12.61,76.37 12.61,76.25 12.52,76.16 12.04,76.16 11.95,76.07 11.95,75.87 12.17,75.65 12.71,75.65 12.94,75.42 12.94,74.15 11.87,73.08 11.87,72.62 12.05,72.45 13.31,72.45 13.86,71.89 13.86,70.87 13.76,70.77 13.37,70.77 13.27,70.67 13.27,66.26 13.12,66.11 12.88,66.11 12.79,66.02 12.79,65.89 12.88,65.8 13.23,65.8 13.32,65.71 13.32,65.59 12.79,65.05 12.79,64.16 11.92,63.3 11.92,60.59 12.27,60.24 12.27,60.01 12.13,59.87 11.94,59.87 11.85,59.78 11.85,59.66 11.96,59.54 12.11,59.54 12.19,59.45 12.19,58.76 12.48,58.48 12.48,57.81 12.42,57.75 12.42,57.33 12.93,56.82 v1(13.4,56.82)
  IN2 w0.102: v1(22.65,76.66) 20.16,76.66 19.69,77.13 13.51,77.13 13.17,77.48 v1(12.61,77.48) 12.61,77.47 11.11,77.47 10.66,77.92 10.36,77.92 9.1,76.66 7.19,76.66 6.84,76.31 5.32,76.31 4.45,77.17 4.45,77.34 4.56,77.45 4.73,77.45 5.52,76.66 v1(6.65,76.66)
  BOTTOM w0.102: 7.76,76.66 v1(6.65,76.66)
  BOTTOM w0.14: v1(22.65,76.66) 22.51,76.52 22.51,76.2 22.65,76.06 22.85,76.06 23.15,76.36 23.28,76.36 U1AM4.L7 ; U1AM2.L7 8.21,76.66 7.76,76.66
M0_MA11: length 59.8
  TOP w0.102: 21.61,80.22 v1(22.65,80.22)
  TOP w0.14: v1(14.2,82.78) 14.08,82.66 14.08,77.1 13.35,76.36 13.35,72.52 13.5,72.37 13.74,72.37 13.88,72.23 13.88,70.77 13.78,70.67 13.21,70.67 13.12,70.58 13.12,70.45 13.21,70.36 13.78,70.36 13.87,70.27 13.87,70.14 13.78,70.04 13.21,70.04 13.12,69.95 13.12,69.82 13.21,69.73 13.78,69.73 13.87,69.64 13.87,69.51 13.78,69.41 13.31,69.41 13.22,69.32 13.22,69.19 13.31,69.1 13.78,69.1 13.87,69.01 13.87,68.88 13.78,68.78 13.34,68.78 13.25,68.69 13.25,68.56 13.34,68.47 13.78,68.47 13.87,68.38 13.87,68.25 13.78,68.15 12.89,68.15 12.8,68.06 12.8,67.93 12.89,67.84 13.78,67.84 13.87,67.75 13.87,65.83 11.41,63.37 11.41,60.76 U1.K25 ; U1AM1.R7 5.49,79.56 6.14,80.22 v1(6.65,80.22) ; U1AM3.R7 20.79,79.56 21.61,80.22
  IN2 w0.102: v1(22.65,80.22) 21.58,80.22 19.01,82.78 17.92,82.78 17.54,82.4 15.53,82.4 15.15,82.78 v1(14.2,82.78) 13.32,82.78 13.22,82.68 10.07,82.68 7.6,80.22 7.22,80.22 6.89,80.55 5.8,80.55 5.7,80.45 5.7,80.29 5.8,80.19 6.63,80.19 v1(6.65,80.22)
  BOTTOM w0.102: 7.63,80.22 v1(6.65,80.22)
  BOTTOM w0.112: 22.84,79.86 22.45,79.86 22.34,79.97 22.34,80.12 22.44,80.22 v1(22.65,80.22)
  BOTTOM w0.14: 22.84,79.86 23.01,79.86 23.31,79.56 U1AM4.R7 ; U1AM2.R7 8.29,79.56 7.63,80.22
M0_MA12: length 57.9
  TOP w0.102: v1(13.4,61.94) 13.08,61.62 U1.M25 ; 21.34,78.08 v1(22.65,78.08)
  TOP w0.14: U1AM3.N7 20.86,77.96 21.22,77.96 21.34,78.08 ; U1AM1.N7 5.68,78.34 6.4,78.34 v1(6.65,78.08)
  IN1 w0.102: v1(14.89,79.99) 15.22,80.32 15.22,80.57 14.92,80.88 14.77,80.88 14.67,80.98 14.67,81.77 14.57,81.87 14.43,81.87 14.33,81.77 14.33,80.67 14.41,80.59 14.68,80.59 14.77,80.5 14.77,80.37 14.68,80.28 14.41,80.28 14.33,80.19 14.33,79.72 14.46,79.59 14.91,79.59 15,79.5 15,79.37 14.91,79.28 14.41,79.28 14.33,79.19 14.33,79.07 14.41,78.98 14.6,78.98 14.69,78.89 14.69,78.76 14.6,78.67 14.41,78.67 14.33,78.59 14.33,78.46 14.41,78.37 14.6,78.37 14.69,78.28 14.69,78.15 14.6,78.06 14.41,78.06 14.33,77.98 14.33,76.26 14.5,76.09 14.5,73.43 15.42,72.51 15.42,65.42 14.31,64.32 14.31,63.53 13.4,62.62 v1(13.4,61.94)
  IN2 w0.102: v1(6.65,78.08) 6.43,78.31 6.11,78.31 6,78.21 6,78.01 6.28,77.73 6.87,77.73 7.22,78.08 8.8,78.08 10.59,79.87 13.13,79.87 13.24,79.99 v1(14.89,79.99) 15.2,79.99 15.29,79.9 15.29,79.77 15.38,79.68 15.51,79.68 15.6,79.77 15.6,79.9 15.69,79.99 15.81,79.99 15.9,79.9 15.9,79.7 15.99,79.61 16.12,79.61 16.21,79.7 16.21,79.9 16.3,79.99 16.44,79.99 16.53,79.9 16.53,79.72 16.62,79.63 16.74,79.63 16.83,79.72 16.83,79.9 16.92,79.99 18.16,79.99 18.25,79.9 18.25,79.65 18.34,79.56 18.47,79.56 18.56,79.65 18.56,80 18.65,80.09 18.8,80.09 18.91,79.98 18.91,79.65 19,79.56 19.9,79.56 21.37,78.08 v1(22.65,78.08)
  BOTTOM w0.102: 7.71,78.08 v1(6.65,78.08)
  BOTTOM w0.14: U1AM4.N7 23.75,78.09 23.6,78.23 23.44,78.23 23.3,78.09 23.3,77.77 23.16,77.63 22.96,77.63 22.65,77.94 v1(22.65,78.08) ; U1AM2.N7 8.03,77.96 7.91,78.08 7.71,78.08
M0_MA13: length 62.1
  TOP w0.102: U1.M23 13.08,59.1 v1(13.4,59.42) ; 22.92,82 v1(22.06,82)
  TOP w0.14: U1AM3.T3 23.78,80.4 23.78,81.13 22.92,82 ; v1(7.25,82) 7.48,82.23 7.68,82.23 8.9,81.01 8.9,80.76 U1AM1.T3
  IN1 w0.102: v1(7.25,82) 8.65,82 8.77,82.12 8.77,82.24 8.37,82.64 8.37,82.76 8.46,82.85 8.59,82.85 9.01,82.43 9.13,82.43 9.22,82.52 9.22,82.65 8.8,83.07 8.8,83.19 9.33,83.72 10.14,83.72 11.47,85.04 12.63,85.04 v1(13.01,84.66) 13.24,84.43 13.24,84.3 13.33,84.21 14.12,84.21 14.21,84.12 14.21,83.99 14.12,83.9 13.33,83.9 13.24,83.81 13.24,83.69 13.33,83.6 14.12,83.6 14.21,83.51 14.21,83.38 14.12,83.29 13.33,83.29 13.24,83.2 13.24,82.73 14.02,81.96 14.02,76.13 14.19,75.96 14.19,73.3 15.11,72.39 15.11,65.55 14.01,64.45 14.01,63.66 13.07,62.72 13.07,61.07 13.4,60.73 v1(13.4,59.42)
  IN2 w0.102: v1(13.01,84.66) 15.43,84.66 15.96,84.13 19.54,84.13 21.68,82 v1(22.06,82)
  BOTTOM w0.102: 6.33,82 v1(7.25,82)
  BOTTOM w0.14: v1(22.06,82) 21.75,82 20.55,80.79 U1AM4.T3 ; U1AM2.T3 5.31,81.3 6,82 6.33,82
M0_MA14: length 62.8
  TOP w0.102: 21.78,81.64 v1(22.65,81.64)
  TOP w0.14: 21.78,81.64 21.42,81.64 20.55,80.77 U1AM3.T7 ; v1(6.65,81.64) 6.65,81.48 6.21,81.03 5.56,81.03 5.31,80.78 U1AM1.T7 ; U1.H25 10.43,63.69 11.55,64.81 11.55,65.45 11.9,65.79 11.9,66.03 11.81,66.13 11.63,66.13 11.53,66.22 11.53,66.35 11.63,66.44 11.81,66.44 11.9,66.53 11.9,66.66 11.81,66.76 11.63,66.76 11.53,66.85 11.53,66.98 11.63,67.07 11.79,67.07 11.88,67.16 11.88,67.29 11.79,67.39 11.63,67.39 11.53,67.48 11.53,67.61 11.63,67.7 11.79,67.7 11.88,67.79 11.88,67.92 11.79,68.02 11.63,68.02 11.53,68.11 11.53,68.24 11.63,68.33 11.79,68.33 11.88,68.42 11.88,68.55 11.79,68.65 11.63,68.65 11.53,68.74 11.53,68.87 11.63,68.96 11.79,68.96 11.88,69.05 11.88,69.18 11.79,69.28 11.63,69.28 11.53,69.37 11.53,69.5 11.63,69.59 11.79,69.59 11.88,69.68 11.88,69.96 11.54,70.29 11.54,72.27 12.43,73.16 12.43,76.74 13.09,77.4 13.09,78.24 12.89,78.44 12.14,78.44 11.55,79.03 11.55,83.82 v1(12.01,84.28)
  IN1 w0.102: v1(12.01,84.28) 11.34,84.28 11.19,84.13 11.19,83.95 11.52,83.62 11.52,83.5 11.43,83.41 11.3,83.41 11,83.71 10.87,83.71 10.78,83.62 10.78,83.5 11.02,83.25 11.02,83.13 10.93,83.04 10.81,83.04 10.56,83.28 10.44,83.28 9.44,82.28 9.44,82.15 9.72,81.87 9.72,81.75 9.63,81.66 9.5,81.66 9.22,81.94 9.1,81.94 9.01,81.85 9.01,81.72 9.29,81.44 9.29,81.32 9.2,81.23 9.07,81.23 8.76,81.54 8.61,81.54 8.53,81.45 8.53,81.32 8.44,81.23 8.31,81.23 8.22,81.32 8.22,81.55 8.13,81.64 8.01,81.64 7.92,81.55 7.92,81.32 7.83,81.23 7.7,81.23 7.61,81.32 7.61,81.55 7.53,81.64 v1(6.65,81.64)
  IN2 w0.102: v1(12.01,84.28) 15.38,84.28 15.83,83.83 19.34,83.83 21.52,81.64 v1(22.65,81.64)
  BOTTOM w0.102: 7.53,81.64 v1(6.65,81.64)
  BOTTOM w0.14: 7.53,81.64 8.51,80.66 U1AM2.T7 ; v1(22.65,81.64) 22.93,81.92 23.35,81.92 23.77,81.5 23.77,80.39 U1AM4.T7
M0_ODT0: length 70.8
  TOP w0.102: 14.68,60.6 14.72,60.55 14.72,60.05 U1.P24
  TOP w0.14: U1AM1.K1 10.28,75.39 10.48,75.39 10.63,75.54 10.63,75.81 10.49,75.95 8.4,75.95 8.09,75.64 8.09,75.33 v1(7.41,74.66) ; 14.68,60.6 14.54,60.74 14.3,60.74 14.13,60.9 14.13,62.11 14.79,62.77 16.26,62.77 16.37,62.88 16.37,63.04 16.26,63.15 15.81,63.15 15.71,63.25 15.71,63.49 15.8,63.59 16.5,63.59 16.59,63.68 16.59,63.81 16.5,63.9 15.81,63.9 15.72,63.99 15.72,64.12 15.81,64.22 16.5,64.22 16.59,64.31 16.59,64.44 16.5,64.53 15.81,64.53 15.72,64.62 15.72,64.75 15.81,64.85 16.5,64.85 16.59,64.94 16.59,65.07 16.5,65.16 15.81,65.16 15.72,65.25 15.72,65.38 15.81,65.48 16.5,65.48 16.59,65.57 16.59,65.7 16.5,65.79 15.81,65.79 15.72,65.88 15.72,70.8 15.82,70.9 16.27,70.9 16.37,71 16.37,71.14 16.27,71.24 15.82,71.24 15.72,71.34 15.72,71.49 15.82,71.59 16.27,71.59 16.37,71.69 16.37,71.83 16.27,71.93 15.82,71.93 15.72,72.03 15.72,72.17 15.82,72.27 16.27,72.27 16.37,72.37 16.37,72.52 16.27,72.62 15.82,72.62 15.72,72.72 15.72,72.86 16.14,73.28 16.14,74.45 v1(15.53,75.06) ; v1(21.84,74.7) 22.16,74.38 22.77,74.38 23.05,74.66 23.05,75.37 23.63,75.95 24.95,75.95 U1AM3.K1
  IN2 w0.102: v1(21.84,74.7) 21.31,74.7 21.18,74.82 21.18,74.99 21.03,75.14 20.88,75.14 20.79,75.05 20.79,74.77 20.7,74.68 20.58,74.68 20.49,74.77 20.49,75.05 20.4,75.14 20.27,75.14 20.18,75.05 20.18,74.85 20.09,74.76 19.97,74.76 19.88,74.85 19.88,75.05 19.79,75.14 19.66,75.14 19.57,75.05 19.57,74.52 19.48,74.43 19.36,74.43 19.27,74.52 19.27,75.32 18.87,75.72 18.74,75.72 18.65,75.63 18.65,75.42 18.56,75.33 17.95,75.33 17.79,75.49 17.79,75.93 17.65,76.06 17.43,76.06 17.31,75.94 17.31,75.24 17.13,75.06 v1(15.53,75.06) 14.18,75.06 13.84,75.4 13.72,75.4 13.59,75.27 13.46,75.27 13.37,75.36 13.37,75.49 13.5,75.62 13.5,75.74 13.24,76 13.1,76 13.01,75.91 13.01,75.56 12.92,75.47 12.8,75.47 12.71,75.56 12.71,75.91 12.62,76 12.49,76 12.4,75.91 12.4,75.71 12.31,75.62 12.19,75.62 12.1,75.71 12.1,75.91 12.01,76 11,76 9.5,74.5 8.14,74.5 7.98,74.66 v1(7.41,74.66)
  BOTTOM w0.102: 6.42,74.34 7.1,74.34
  BOTTOM w0.14: U1AM4.K1 19.23,75.56 19.62,75.17 21.07,75.17 21.21,75.03 21.21,74.83 21.06,74.67 21.06,74.42 21.31,74.18 21.5,74.18 21.84,74.52 v1(21.84,74.7) ; 7.1,74.34 v1(7.41,74.66) ; v1(15.53,75.06) 15.34,75.06 14.81,74.53 R1AM21.2 ; U1AM2.K1 4.12,75.97 5.45,75.97 6.12,75.31 6.12,74.64 6.42,74.34
M0_RASB: length 58.6
  TOP w0.102: U1.N22 v1(14.08,58.78)
  TOP w0.14: U1AM1.J3 8.77,74.76 8.88,74.66 8.88,74.46 8.78,74.36 8.35,74.36 7.76,73.77 7.56,73.77 v1(7.41,73.91) ; v1(21.89,73.99) 22.07,73.99 22.38,73.67 22.39,73.67 22.5,73.56 22.84,73.56 23.75,74.47 U1AM3.J3
  IN1 w0.102: v1(15.25,74.27) 15.12,74.4 15.12,74.58 15.22,74.68 16.33,74.68 16.43,74.58 16.43,74.05 16.33,73.94 15.25,73.94 15.15,73.84 15.15,73.65 15.61,73.18 15.91,73.18 16.04,73.06 16.04,70.63 16.12,70.54 16.25,70.54 16.34,70.45 16.34,70.32 16.25,70.23 16.12,70.23 16.04,70.14 16.04,68.65 16.12,68.56 16.43,68.56 16.52,68.47 16.52,68.34 16.43,68.25 16.12,68.25 16.04,68.16 16.04,68.04 16.12,67.95 16.46,67.95 16.55,67.86 16.55,67.73 16.46,67.64 16.12,67.64 16.04,67.55 16.04,67.43 16.12,67.34 16.63,67.34 16.72,67.25 16.72,67.12 16.63,67.03 16.12,67.03 16.04,66.94 16.04,65.15 15.94,65.05 15.94,64.95 16.04,64.85 16.04,64.66 15.95,64.57 15.44,64.57 15.35,64.48 15.35,64.36 15.44,64.27 15.95,64.27 16.04,64.18 16.04,64.05 15.95,63.96 15.01,63.96 14.92,63.87 14.92,63.75 15.01,63.66 16.5,63.66 16.6,63.56 16.6,63.41 16.46,63.28 14.92,63.28 14.16,62.51 14.16,61.55 13.74,61.13 13.74,59.74 13.83,59.65 14.12,59.65 14.21,59.57 14.21,59.44 14.12,59.35 13.83,59.35 13.74,59.26 13.74,57.9 13.84,57.8 14.01,57.8 14.11,57.89 14.11,58.76 v1(14.08,58.78)
  IN2 w0.102: v1(21.89,73.99) 20.85,73.99 20.09,73.23 19.87,73.23 19.78,73.32 19.78,73.44 19.87,73.54 19.87,73.67 19.78,73.76 19.66,73.76 19.44,73.53 19.29,73.53 18.53,74.3 15.27,74.3 v1(15.25,74.27) 14.11,74.27 13.78,74.6 12,74.6 11.54,75.06 10.93,75.06 9.76,73.89 7.43,73.89 v1(7.41,73.91)
  BOTTOM w0.102: 6.23,73.59 6.79,73.59 7.11,73.91
  BOTTOM w0.14: U1AM4.J3 20.55,74.46 20.9,74.11 20.9,74.1 21.35,73.65 21.75,73.65 21.89,73.79 v1(21.89,73.99) ; U1AM2.J3 5.31,74.51 6.23,73.59 ; 7.11,73.91 v1(7.41,73.91)
M0_WEB: length 60.7
  TOP w0.102: v1(14.74,57.49) 14.43,57.8 U1.P21
  TOP w0.14: v1(6.58,75.48) 7,75.06 7.38,75.06 7.73,75.41 7.73,75.71 8.38,76.36 U1AM1.L3 ; v1(22.48,75.47) 22.71,75.47 23.6,76.36 U1AM3.L3
  IN1 w0.102: v1(14.74,57.49) 14.74,57.28 14.87,57.16 15.58,57.16 15.68,57.26 15.68,57.59 15.59,57.68 15.14,57.68 15.05,57.77 15.05,57.9 15.14,57.99 15.59,57.99 15.68,58.07 15.68,58.2 15.59,58.29 15.17,58.29 15.07,58.39 15.07,59.59 14.97,59.7 14.97,60.13 15.62,60.77 15.62,61.56 16.22,62.16 17.08,62.16 17.94,63.02 17.94,68.05 17.76,68.23 17.76,70.77 17.34,71.19 17.34,75.98 17.28,76.04 17.28,76.64 17.38,76.74 17.69,76.74 17.79,76.84 17.79,77.02 17.69,77.12 17.03,77.12 16.93,77.02 v1(16.93,75.69)
  IN2 w0.102: v1(6.58,75.48) 7.02,75.04 8.04,75.04 8.27,74.81 9.37,74.81 10.87,76.31 13.37,76.31 14.26,75.42 16.65,75.42 v1(16.93,75.69) 17,75.77 17,76.15 17.31,76.46 17.69,76.46 18.07,76.08 18.96,76.08 19.59,75.44 21.16,75.44 21.55,75.05 22.4,75.05 22.47,75.13 23.31,75.13 24.06,75.88 24.91,75.88 25.03,76 25.03,76.23 24.93,76.33 23.89,76.33 23.03,75.47 v1(22.48,75.47)
  BOTTOM w0.14: U1AM2.L3 5.52,76.36 6.4,75.48 v1(6.58,75.48) ; v1(22.48,75.47) 22.08,75.87 21.99,75.87 21.5,76.36 21.12,76.36 U1AM4.L3
MDSI_COMP: length 1.2
  TOP w0.254: v1(14.07,44.23) 14.4,44.56 U1.P1
  BOTTOM w0.254: v1(14.07,44.23) 14.71,44.23 R1AS41.2
MSCI_COMP: length 2.2
  TOP w0.112: R1AS42.2 12.05,43.09 12.05,44.28 U1.K1
NC_VSDIO: length 4.9
  TOP w0.203: U1AP1.39 18.25,26.09
  TOP w0.457: C1AP28.1 19.68,24.22 19.68,24.23 19.44,24.47 19.44,24.48 v1(19.25,24.67) 18.25,25.66 18.25,26.09
  BOTTOM w0.457: v1(19.25,24.67) 19.34,24.57 R1AP11.1
P0_REXT: length 4.1
  TOP w0.152: U1.C1 5.12,42.54 R1AS13.1
P1_REXT: length 2.4
  TOP w0.254: U1.A8 5.8,49.13 5.8,48.88 5.56,48.65 4.13,48.65 R1AS10.1
PLTRST_N: length 20.4
  TOP w0.102: U1.B6 6.16,47.53 6.16,46.89 v1(6.11,46.84) ; v1(14.11,35.49) 14.55,35.04 U1AP1.65
  IN1 w0.102: v1(6,39.53) 6,39.78 6.67,40.44 6.67,46.28 v1(6.11,46.84)
  IN2 w0.102: v1(14.11,35.49) 13.09,36.5 8.05,36.5 6.36,38.2 6.36,38.97 6,39.32 v1(6,39.53)
PMIC_USB2_DN: length 22.5
  TOP w0.131: v1(15.13,26.58) 15,26.58 14.87,26.46 14.87,26.19 14.95,26.11 U1AP1.32 ; L1USB3.2 26.66,35.59 26.98,35.91 26.98,36.08 26.84,36.22 26.57,36.22 26.38,36.03 25.97,36.03 25.78,36.03 25.54,36.28 25.36,36.28 25.26,36.18 v1(25.26,36.03)
  IN1 w0.117: v1(15.13,26.58) 14.96,26.58 14.81,26.74 14.81,30.45 15.71,31.35 20.96,31.35 24.45,34.83 24.45,36.2 24.79,36.54 25.04,36.54 25.32,36.26 25.32,36.09 v1(25.26,36.03)
PMIC_USB2_DN_C: length 3.1
  TOP w0.131: L1USB3.1 26.66,33.83 26.8,33.69 26.8,33.39 27.07,33.12 27.44,33.12 27.66,33.35 J1P1.2
PMIC_USB2_DP: length 22.6
  TOP w0.131: v1(25.78,36.55) 25.78,36.36 25.88,36.26 26.29,36.26 26.48,36.45 26.93,36.45 27.21,36.18 L1USB3.3 ; U1AP1.31 14.55,26.1 14.64,26.19 14.64,26.33 v1(14.39,26.58)
  IN1 w0.117: v1(25.78,36.55) 25.41,36.55 25.16,36.81 24.67,36.81 24.18,36.31 24.18,34.95 20.85,31.62 15.6,31.62 14.54,30.56 14.54,26.73 v1(14.39,26.58)
PMIC_USB2_DP_C: length 3
  TOP w0.131: J1P1.3 28.16,34 28.08,33.91 28.08,33.65 28.01,33.58 27.57,33.58 27.34,33.36 27.17,33.36 27.04,33.49 27.04,33.66 27.21,33.83 L1USB3.4
